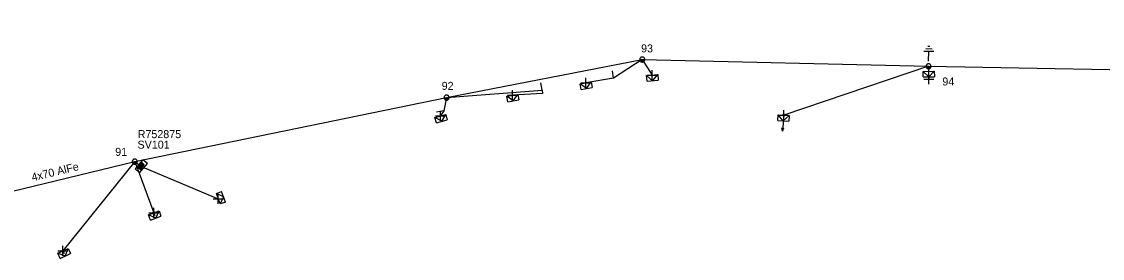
# Model space of a CAD drawing. Extents: x -544780 to -541582, y -1198995 to -1196551.
# Drawn here: x -541985.1 to -541850, y -1198825.9 to -1198796.3 of the extents above; entities that cross this region are included whole.
import ezdxf

# ---------------------------------------------------------------- set-up
doc = ezdxf.new("R2010")
doc.units = 0
for name, color, linetype in [('Vrstva 1', 7, 'Continuous'), ('Vrstva 13', 7, 'Continuous'), ('Vrstva 14', 7, 'Continuous'), ('Vrstva 15', 7, 'Continuous'), ('Vrstva 2', 7, 'Continuous'), ('Vrstva 28', 7, 'Continuous'), ('Vrstva 29', 7, 'Continuous'), ('Vrstva 30', 7, 'Continuous'), ('Vrstva 31', 7, 'Continuous'), ('Vrstva 34', 7, 'Continuous'), ('Vrstva 5', 7, 'Continuous'), ('Vrstva 52', 7, 'Continuous'), ('Vrstva 54', 7, 'Continuous'), ('Vrstva 8', 7, 'Continuous'), ('Vrstva 9', 7, 'Continuous')]:
    doc.layers.add(name, color=color, linetype=linetype)

# ---------------------------------------------------------------- blocks, each defined once
blk = doc.blocks.new('NN440')
at = {"layer": 'Vrstva 2'}
for points in [[(0.63, 0), (0.63, 0.06), (0.62, 0.13), (0.6, 0.19), (0.58, 0.25), (0.55, 0.31), (0.51, 0.37), (0.47, 0.42), (0.42, 0.46), (0.37, 0.51), (0.32, 0.54), (0.26, 0.57), (0.2, 0.59), (0.13, 0.61), (0.07, 0.62), (0, 0.63), (-0.06, 0.62), (-0.13, 0.61), (-0.19, 0.59), (-0.26, 0.57), (-0.31, 0.54), (-0.37, 0.51), (-0.42, 0.46), (-0.47, 0.42), (-0.51, 0.37), (-0.54, 0.31), (-0.57, 0.25), (-0.6, 0.19), (-0.62, 0.13), (-0.63, 0.06), (-0.63, 0), (-0.63, -0.07), (-0.62, -0.14), (-0.6, -0.2), (-0.57, -0.26), (-0.54, -0.32), (-0.51, -0.37), (-0.47, -0.43), (-0.42, -0.47), (-0.37, -0.51), (-0.31, -0.55), (-0.26, -0.58), (-0.19, -0.6), (-0.13, -0.62), (-0.06, -0.63), (0, -0.63), (0.07, -0.63), (0.13, -0.62), (0.2, -0.6), (0.26, -0.58), (0.32, -0.55), (0.37, -0.51), (0.42, -0.47), (0.47, -0.43), (0.51, -0.37), (0.55, -0.32), (0.58, -0.26), (0.6, -0.2), (0.62, -0.14), (0.63, -0.07), (0.63, 0)], [(-0.63, 0), (0.63, 0)], [(-0.6, -0.18), (0.57, -0.18)], [(-0.51, -0.32), (0.5, -0.32)], [(-0.37, -0.47), (0.35, -0.47)]]:
    blk.add_lwpolyline(points, dxfattribs=at)
blk = doc.blocks.new('NN560')
at = {"layer": 'Vrstva 2'}
for points in [[(2, 0), (1.59, 0.14)], [(0, 0), (2, 0)], [(2, 0), (1.59, -0.13)]]:
    blk.add_lwpolyline(points, dxfattribs=at)
blk = doc.blocks.new('NN800')
at = {"layer": 'Vrstva 1'}
for points in [[(-0.44, 0.44), (0.44, -0.44)], [(-0.44, -0.44), (0.44, 0.44)]]:
    blk.add_lwpolyline(points, dxfattribs=at)
blk = doc.blocks.new('NN620')
at = {"layer": 'Vrstva 8'}
for points in [[(0.75, 0), (-0.75, 0)], [(-0.75, 0), (-0.75, -0.75)], [(0.75, -0.75), (0.75, 0)], [(-0.75, -0.75), (0.75, -0.75)], [(0.37, -0.18), (-0.38, -0.18)], [(-0.38, -0.18), (-0.38, -0.56)], [(-0.38, -0.56), (0.37, -0.56)], [(0.32, -0.23), (-0.33, -0.23)], [(-0.33, -0.23), (-0.33, -0.51)], [(-0.33, -0.51), (0.32, -0.51)], [(0.27, -0.27), (-0.28, -0.27)], [(-0.28, -0.27), (-0.28, -0.46)], [(-0.28, -0.46), (0.27, -0.46)], [(0.23, -0.32), (-0.23, -0.32)], [(-0.23, -0.32), (-0.23, -0.42)], [(-0.23, -0.42), (0.23, -0.42)], [(-0.19, -0.37), (0.19, -0.37)], [(0.23, -0.42), (0.23, -0.32)], [(0.27, -0.46), (0.27, -0.27)], [(0.32, -0.51), (0.32, -0.23)], [(0.37, -0.56), (0.37, -0.18)]]:
    blk.add_lwpolyline(points, dxfattribs=at)
blk = doc.blocks.new('NN630')
at = {"layer": 'Vrstva 9'}
for points in [[(0, -0.7), (-0.7, 0)], [(-0.7, -0.7), (-0.7, 0), (0.7, 0), (0.7, -0.7)], [(-0.7, -0.7), (0.7, -0.7)], [(0, -0.7), (0.7, 0)]]:
    blk.add_lwpolyline(points, dxfattribs=at)
blk = doc.blocks.new('NN810')
at = {"layer": 'Vrstva 14'}
for points in [[(0, -0.64), (0, -1.89)], [(0.63, -1.89), (-0.62, -1.89)], [(0.39, -2.2), (-0.4, -2.2)], [(0, -2.52), (-0.12, -2.52)], [(0.14, -2.52), (0, -2.52)]]:
    blk.add_lwpolyline(points, dxfattribs=at)
blk = doc.blocks.new('NN500')
at = {"layer": 'Vrstva 2'}
for points in [[(0, -0.24), (0.02, -0.23), (0.05, -0.23), (0.07, -0.22), (0.09, -0.22), (0.12, -0.2), (0.14, -0.19), (0.16, -0.18), (0.17, -0.16), (0.19, -0.14), (0.2, -0.12), (0.21, -0.1), (0.22, -0.07), (0.23, -0.05), (0.23, -0.02), (0.23, 0), (0.23, 0.02), (0.23, 0.05), (0.22, 0.07), (0.21, 0.1), (0.2, 0.12), (0.19, 0.14), (0.17, 0.16), (0.16, 0.17), (0.14, 0.19), (0.12, 0.2), (0.09, 0.21), (0.07, 0.22), (0.05, 0.23), (0.02, 0.23), (0, 0.23), (-0.03, 0.23), (-0.05, 0.23), (-0.07, 0.22), (-0.1, 0.21), (-0.12, 0.2), (-0.14, 0.19), (-0.16, 0.17), (-0.18, 0.16), (-0.19, 0.14), (-0.2, 0.12), (-0.22, 0.1), (-0.22, 0.07), (-0.23, 0.05), (-0.23, 0.02), (-0.24, 0), (-0.23, -0.02), (-0.23, -0.05), (-0.22, -0.07), (-0.22, -0.1), (-0.2, -0.12), (-0.19, -0.14), (-0.18, -0.16), (-0.16, -0.18), (-0.14, -0.19), (-0.12, -0.2), (-0.1, -0.22), (-0.07, -0.22), (-0.05, -0.23), (-0.03, -0.23), (0, -0.24)], [(0, -0.24), (0.02, -0.23), (0.05, -0.23), (0.07, -0.22), (0.09, -0.22), (0.12, -0.2), (0.14, -0.19), (0.16, -0.18), (0.17, -0.16), (0.19, -0.14), (0.2, -0.12), (0.21, -0.1), (0.22, -0.07), (0.23, -0.05), (0.23, -0.02), (0.23, 0), (0.23, 0.02), (0.23, 0.05), (0.22, 0.07), (0.21, 0.1), (0.2, 0.12), (0.19, 0.14), (0.17, 0.16), (0.16, 0.17), (0.14, 0.19), (0.12, 0.2), (0.09, 0.21), (0.07, 0.22), (0.05, 0.23), (0.02, 0.23), (0, 0.23), (-0.03, 0.23), (-0.05, 0.23), (-0.07, 0.22), (-0.1, 0.21), (-0.12, 0.2), (-0.14, 0.19), (-0.16, 0.17), (-0.18, 0.16), (-0.19, 0.14), (-0.2, 0.12), (-0.22, 0.1), (-0.22, 0.07), (-0.23, 0.05), (-0.23, 0.02), (-0.24, 0), (-0.23, -0.02), (-0.23, -0.05), (-0.22, -0.07), (-0.22, -0.1), (-0.2, -0.12), (-0.19, -0.14), (-0.18, -0.16), (-0.16, -0.18), (-0.14, -0.19), (-0.12, -0.2), (-0.1, -0.22), (-0.07, -0.22), (-0.05, -0.23), (-0.03, -0.23), (0, -0.24)], [(0, -0.21), (0.02, -0.2), (0.04, -0.2), (0.06, -0.2), (0.08, -0.19), (0.1, -0.18), (0.12, -0.17), (0.14, -0.15), (0.15, -0.14), (0.16, -0.12), (0.18, -0.1), (0.19, -0.08), (0.19, -0.06), (0.2, -0.04), (0.2, -0.02), (0.2, 0), (0.2, 0.02), (0.2, 0.04), (0.19, 0.06), (0.19, 0.08), (0.18, 0.1), (0.16, 0.12), (0.15, 0.14), (0.14, 0.15), (0.12, 0.17), (0.1, 0.18), (0.08, 0.19), (0.06, 0.19), (0.04, 0.2), (0.02, 0.2), (0, 0.2), (-0.02, 0.2), (-0.04, 0.2), (-0.06, 0.19), (-0.08, 0.19), (-0.1, 0.18), (-0.12, 0.17), (-0.14, 0.15), (-0.15, 0.14), (-0.17, 0.12), (-0.18, 0.1), (-0.19, 0.08), (-0.2, 0.06), (-0.2, 0.04), (-0.21, 0.02), (-0.21, 0), (-0.21, -0.02), (-0.2, -0.04), (-0.2, -0.06), (-0.19, -0.08), (-0.18, -0.1), (-0.17, -0.12), (-0.15, -0.14), (-0.14, -0.15), (-0.12, -0.17), (-0.1, -0.18), (-0.08, -0.19), (-0.06, -0.2), (-0.04, -0.2), (-0.02, -0.2), (0, -0.21)], [(0, -0.18), (0.02, -0.18), (0.04, -0.17), (0.05, -0.17), (0.07, -0.16), (0.09, -0.15), (0.1, -0.14), (0.12, -0.13), (0.13, -0.12), (0.14, -0.1), (0.15, -0.09), (0.16, -0.07), (0.17, -0.05), (0.17, -0.04), (0.17, -0.02), (0.17, 0), (0.17, 0.02), (0.17, 0.04), (0.17, 0.05), (0.16, 0.07), (0.15, 0.09), (0.14, 0.1), (0.13, 0.12), (0.12, 0.13), (0.1, 0.14), (0.09, 0.15), (0.07, 0.16), (0.05, 0.17), (0.04, 0.17), (0.02, 0.17), (0, 0.18), (-0.02, 0.17), (-0.04, 0.17), (-0.06, 0.17), (-0.07, 0.16), (-0.09, 0.15), (-0.1, 0.14), (-0.12, 0.13), (-0.13, 0.12), (-0.14, 0.1), (-0.15, 0.09), (-0.16, 0.07), (-0.17, 0.05), (-0.17, 0.04), (-0.18, 0.02), (-0.18, 0), (-0.18, -0.02), (-0.17, -0.04), (-0.17, -0.05), (-0.16, -0.07), (-0.15, -0.09), (-0.14, -0.1), (-0.13, -0.12), (-0.12, -0.13), (-0.1, -0.14), (-0.09, -0.15), (-0.07, -0.16), (-0.06, -0.17), (-0.04, -0.17), (-0.02, -0.18), (0, -0.18)], [(0, -0.15), (0.01, -0.15), (0.03, -0.14), (0.04, -0.14), (0.06, -0.13), (0.07, -0.13), (0.08, -0.12), (0.1, -0.11), (0.11, -0.1), (0.12, -0.09), (0.13, -0.07), (0.13, -0.06), (0.14, -0.05), (0.14, -0.03), (0.14, -0.02), (0.14, 0), (0.14, 0.01), (0.14, 0.03), (0.14, 0.04), (0.13, 0.06), (0.13, 0.07), (0.12, 0.09), (0.11, 0.1), (0.1, 0.11), (0.08, 0.12), (0.07, 0.13), (0.06, 0.13), (0.04, 0.14), (0.03, 0.14), (0.01, 0.14), (0, 0.15), (-0.02, 0.14), (-0.03, 0.14), (-0.05, 0.14), (-0.06, 0.13), (-0.07, 0.13), (-0.09, 0.12), (-0.1, 0.11), (-0.11, 0.1), (-0.12, 0.09), (-0.13, 0.07), (-0.13, 0.06), (-0.14, 0.04), (-0.14, 0.03), (-0.15, 0.01), (-0.15, 0), (-0.15, -0.02), (-0.14, -0.03), (-0.14, -0.05), (-0.13, -0.06), (-0.13, -0.07), (-0.12, -0.09), (-0.11, -0.1), (-0.1, -0.11), (-0.09, -0.12), (-0.07, -0.13), (-0.06, -0.13), (-0.05, -0.14), (-0.03, -0.14), (-0.02, -0.15), (0, -0.15)], [(0, -0.12), (0.01, -0.12), (0.02, -0.11), (0.03, -0.11), (0.05, -0.11), (0.06, -0.1), (0.07, -0.09), (0.08, -0.09), (0.09, -0.08), (0.09, -0.07), (0.1, -0.06), (0.11, -0.05), (0.11, -0.04), (0.11, -0.02), (0.11, -0.01), (0.12, 0), (0.11, 0.01), (0.11, 0.02), (0.11, 0.04), (0.11, 0.05), (0.1, 0.06), (0.09, 0.07), (0.09, 0.08), (0.08, 0.09), (0.07, 0.09), (0.06, 0.1), (0.05, 0.11), (0.03, 0.11), (0.02, 0.11), (0.01, 0.12), (0, 0.12), (-0.01, 0.12), (-0.03, 0.11), (-0.04, 0.11), (-0.05, 0.11), (-0.06, 0.1), (-0.07, 0.09), (-0.08, 0.09), (-0.09, 0.08), (-0.1, 0.07), (-0.1, 0.06), (-0.11, 0.05), (-0.11, 0.04), (-0.12, 0.02), (-0.12, 0.01), (-0.12, 0), (-0.12, -0.01), (-0.12, -0.02), (-0.11, -0.04), (-0.11, -0.05), (-0.1, -0.06), (-0.1, -0.07), (-0.09, -0.08), (-0.08, -0.09), (-0.07, -0.09), (-0.06, -0.1), (-0.05, -0.11), (-0.04, -0.11), (-0.03, -0.11), (-0.01, -0.12), (0, -0.12)], [(0, -0.09), (0.01, -0.09), (0.02, -0.09), (0.03, -0.08), (0.03, -0.08), (0.04, -0.08), (0.05, -0.07), (0.06, -0.07), (0.06, -0.06), (0.07, -0.05), (0.07, -0.04), (0.08, -0.04), (0.08, -0.03), (0.08, -0.02), (0.09, -0.01), (0.09, 0), (0.09, 0.01), (0.08, 0.02), (0.08, 0.03), (0.08, 0.03), (0.07, 0.04), (0.07, 0.05), (0.06, 0.06), (0.06, 0.06), (0.05, 0.07), (0.04, 0.07), (0.03, 0.08), (0.03, 0.08), (0.02, 0.08), (0.01, 0.09), (0, 0.09), (-0.01, 0.09), (-0.02, 0.08), (-0.03, 0.08), (-0.04, 0.08), (-0.04, 0.07), (-0.05, 0.07), (-0.06, 0.06), (-0.07, 0.06), (-0.07, 0.05), (-0.08, 0.04), (-0.08, 0.03), (-0.08, 0.03), (-0.09, 0.02), (-0.09, 0.01), (-0.09, 0), (-0.09, -0.01), (-0.09, -0.02), (-0.08, -0.03), (-0.08, -0.04), (-0.08, -0.04), (-0.07, -0.05), (-0.07, -0.06), (-0.06, -0.07), (-0.05, -0.07), (-0.04, -0.08), (-0.04, -0.08), (-0.03, -0.08), (-0.02, -0.09), (-0.01, -0.09), (0, -0.09)], [(0, -0.06), (0, -0.06), (0.01, -0.06), (0.02, -0.05), (0.02, -0.05), (0.03, -0.05), (0.03, -0.05), (0.04, -0.04), (0.04, -0.04), (0.05, -0.03), (0.05, -0.03), (0.05, -0.02), (0.05, -0.02), (0.05, -0.01), (0.06, -0.01), (0.06, 0), (0.06, 0.01), (0.05, 0.01), (0.05, 0.02), (0.05, 0.02), (0.05, 0.03), (0.05, 0.03), (0.04, 0.04), (0.04, 0.04), (0.03, 0.05), (0.03, 0.05), (0.02, 0.05), (0.02, 0.05), (0.01, 0.06), (0, 0.06), (0, 0.06), (-0.01, 0.06), (-0.01, 0.06), (-0.02, 0.05), (-0.02, 0.05), (-0.03, 0.05), (-0.03, 0.05), (-0.04, 0.04), (-0.04, 0.04), (-0.05, 0.03), (-0.05, 0.03), (-0.05, 0.02), (-0.06, 0.02), (-0.06, 0.01), (-0.06, 0.01), (-0.06, 0), (-0.06, -0.01), (-0.06, -0.01), (-0.06, -0.02), (-0.05, -0.02), (-0.05, -0.03), (-0.05, -0.03), (-0.04, -0.04), (-0.04, -0.04), (-0.03, -0.05), (-0.03, -0.05), (-0.02, -0.05), (-0.02, -0.05), (-0.01, -0.06), (-0.01, -0.06), (0, -0.06)], [(0, -0.03), (0, -0.03), (0, -0.03), (0.01, -0.03), (0.01, -0.03), (0.01, -0.02), (0.02, -0.02), (0.02, -0.02), (0.02, -0.02), (0.02, -0.02), (0.02, -0.01), (0.02, -0.01), (0.03, -0.01), (0.03, -0.01), (0.03, 0), (0.03, 0), (0.03, 0), (0.03, 0.01), (0.03, 0.01), (0.02, 0.01), (0.02, 0.01), (0.02, 0.02), (0.02, 0.02), (0.02, 0.02), (0.02, 0.02), (0.01, 0.02), (0.01, 0.02), (0.01, 0.03), (0, 0.03), (0, 0.03), (0, 0.03), (0, 0.03), (-0.01, 0.03), (-0.01, 0.03), (-0.01, 0.02), (-0.02, 0.02), (-0.02, 0.02), (-0.02, 0.02), (-0.02, 0.02), (-0.02, 0.02), (-0.03, 0.01), (-0.03, 0.01), (-0.03, 0.01), (-0.03, 0.01), (-0.03, 0), (-0.03, 0), (-0.03, 0), (-0.03, -0.01), (-0.03, -0.01), (-0.03, -0.01), (-0.03, -0.01), (-0.02, -0.02), (-0.02, -0.02), (-0.02, -0.02), (-0.02, -0.02), (-0.02, -0.02), (-0.01, -0.03), (-0.01, -0.03), (-0.01, -0.03), (0, -0.03), (0, -0.03)], [(0.23, 0), (0.7, 0)]]:
    blk.add_lwpolyline(points, dxfattribs=at)
blk = doc.blocks.new('NN510')
at = {"layer": 'Vrstva 2'}
blk.add_lwpolyline([(0, 0), (0, 0.94)], dxfattribs=at)

msp = doc.modelspace()

# ---------------------------------------------------------------- linework, layer by layer
at = {"layer": 'Vrstva 1'}
for points in [[(-541970.92, -1198813.83), (-541931.95, -1198805.83), (-541907.49, -1198801.08), (-541871.72, -1198801.93), (-541835.54, -1198802.58), (-541796.52, -1198796.35)], [(-542001.85, -1198821.31), (-541970.92, -1198813.83)]]:
    msp.add_lwpolyline(points, dxfattribs=at)
at = {"layer": 'Vrstva 5'}
msp.add_lwpolyline([(-541970.92, -1198813.83), (-541970.4, -1198814.17)], dxfattribs=at)
at = {"layer": 'Vrstva 52'}
for points in [[(-541907.49, -1198801.08), (-541906.26, -1198803.03)], [(-541871.72, -1198801.93), (-541871.7, -1198802.55), (-541871.69, -1198803.53)], [(-541969.83, -1198814.54), (-541969.7, -1198814.62), (-541960.48, -1198818.46)]]:
    msp.add_lwpolyline(points, dxfattribs=at)
at = {"layer": 'Vrstva 54'}
for points in [[(-541907.49, -1198801.08), (-541911.07, -1198803.41), (-541914.56, -1198804)], [(-541871.72, -1198801.93), (-541889.82, -1198808.03)], [(-541931.95, -1198805.83), (-541932.28, -1198807.49), (-541932.71, -1198808.12)], [(-541931.95, -1198805.83), (-541920.02, -1198804.92), (-541919.96, -1198805.34), (-541923.73, -1198805.55)], [(-541970.92, -1198813.83), (-541979.89, -1198824.98)], [(-541970.92, -1198813.83), (-541968.54, -1198820.23)]]:
    msp.add_lwpolyline(points, dxfattribs=at)

# ---------------------------------------------------------------- block references
at = {"layer": 'Vrstva 13'}
for name, p, xscale, yscale, rotation in [('NN440', (-541907.49, -1198801.08), 0.5, 0.5, 10.989747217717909), ('NN440', (-541871.72, -1198801.93), 0.5000000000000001, 0.5, -1.3612582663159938), ('NN440', (-541931.95, -1198805.83), 0.5, 0.5, 11.600858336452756), ('NN500', (-541889.82, -1198808.03), 0.49999999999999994, 0.5, -93.74300005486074), ('NN440', (-541970.92, -1198813.83), 0.5000000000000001, 0.5, 13.595602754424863), ('NN500', (-541968.54, -1198820.23), 0.5, 0.5000000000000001, -69.69600003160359), ('NN500', (-541979.89, -1198824.98), 0.5, 0.5, -65.18300004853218)]:
    msp.add_blockref(name, p, dxfattribs=dict(at, xscale=xscale, yscale=yscale, rotation=rotation))
for name, p, rotation in [('NN510', (-541911.07, -1198803.41), 9.58699164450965), ('NN510', (-541920.02, -1198804.92), 9.556527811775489), ('NN510', (-541932.28, -1198807.49), 99.44347497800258), ('NN560', (-541889.82, -1198808.03), -93.7426667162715)]:
    msp.add_blockref(name, p, dxfattribs=dict(at, rotation=rotation))
at = {"layer": 'Vrstva 15', "rotation": 178.63874173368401}
msp.add_blockref('NN810', (-541871.72, -1198801.93), dxfattribs=at)
at = {"layer": 'Vrstva 28', "rotation": 50.057806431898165}
msp.add_blockref('NN620', (-541970.4, -1198814.17), dxfattribs=at)
at = {"layer": 'Vrstva 31'}
for p, rotation in [((-541906.26, -1198803.03), 5.000644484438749), ((-541871.7, -1198802.55), 0.7406556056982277), ((-541914.56, -1198804), 9.58699164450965), ((-541923.73, -1198805.55), 9.462322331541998), ((-541932.72, -1198808.12), 15.306338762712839), ((-541889.82, -1198808.03), -3.7426666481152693), ((-541960.48, -1198818.46), 110.1682667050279), ((-541968.54, -1198820.23), 20.30395547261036), ((-541979.89, -1198824.98), 24.817341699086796)]:
    msp.add_blockref('NN630', p, dxfattribs=dict(at, rotation=rotation))
at = {"layer": 'Vrstva 34'}
for p, rotation in [((-541906.26, -1198803.03), 45), ((-541871.69, -1198803.53), 44.99999995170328), ((-541914.56, -1198804), 45), ((-541923.73, -1198805.55), 45), ((-541932.71, -1198808.12), 45.00000009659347), ((-541889.82, -1198808.03), 45), ((-541960.48, -1198818.46), 45), ((-541968.54, -1198820.23), 45), ((-541979.89, -1198824.98), 45)]:
    msp.add_blockref('NN800', p, dxfattribs=dict(at, rotation=rotation))

# ---------------------------------------------------------------- texts
at = {"layer": 'Vrstva 14'}
for s, p in [('93', (-541907.64, -1198800.19)), ('92', (-541932.56, -1198804.87)), ('94', (-541869.99, -1198804.32)), ('91', (-541973.36, -1198813.11))]:
    msp.add_text(s, height=1, dxfattribs=at).set_placement(p)
at = {"layer": 'Vrstva 2'}
msp.add_text('4x70 AlFe', height=1, rotation=13.596, dxfattribs=at).set_placement((-541983.69, -1198816.29))
at = {"layer": 'Vrstva 29'}
msp.add_text('R752875', height=1, dxfattribs=at).set_placement((-541970.55, -1198810.9))
at = {"layer": 'Vrstva 30'}
msp.add_text('SV101', height=1, dxfattribs=at).set_placement((-541970.57, -1198812.21))

doc.saveas('drawing.dxf')
